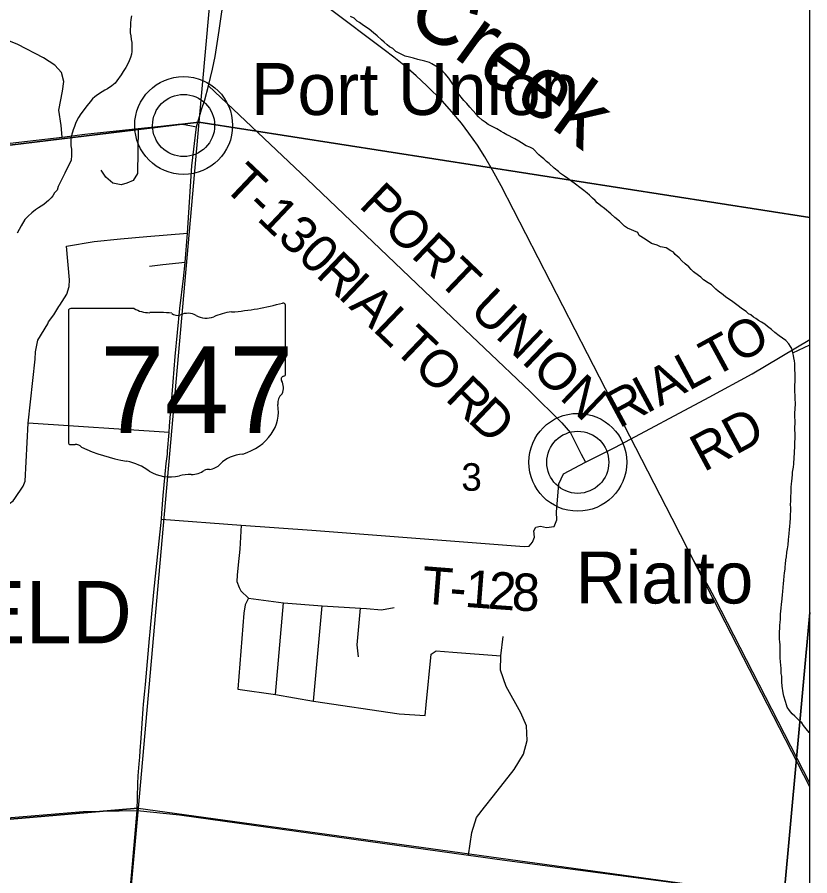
# Model space of a CAD drawing. Extents: x 0 to 34, y 0 to 22.
# Drawn here: x 14.895 to 16.1, y 15.978 to 17.283 of the extents above; entities that cross this region are included whole.
import ezdxf

# ---------------------------------------------------------------- set-up
doc = ezdxf.new("R2010")
doc.units = 0
for name, color, linetype in [('GM_X_City_Street', 7, 'Continuous'), ('GM_X_Corporation_Text', 7, 'Continuous'), ('GM_X_County_Road', 7, 'Continuous'), ('GM_X_Minor_River', 7, 'Continuous'), ('GM_X_Minor_River_Text', 7, 'Continuous'), ('GM_X_Rail_Line', 7, 'Continuous'), ('GM_X_Section', 7, 'Continuous'), ('GM_X_Section_Text', 7, 'Continuous'), ('GM_X_State_Location', 7, 'Continuous'), ('GM_X_State_Route', 7, 'Continuous'), ('GM_X_State_Shield', 7, 'Continuous'), ('GM_X_Township_Road', 7, 'Continuous'), ('GM_X_Township_Road_Text', 7, 'Continuous'), ('GM_X_Unincorporated', 7, 'Continuous'), ('GM_X_Unincorporated_Location', 7, 'Continuous'), ('GM_X_Unincorporated_Text', 7, 'Continuous'), ('SC_Scratch1', 7, 'Continuous'), ('SH_Border', 7, 'Continuous'), ('SH_Cut_Line', 7, 'Continuous')]:
    doc.layers.add(name, color=color, linetype=linetype)

msp = doc.modelspace()

# ---------------------------------------------------------------- linework, layer by layer
at = {"layer": 'GM_X_City_Street'}
msp.add_lwpolyline([(15.1505, 16.9097), (15.1165, 16.9063), (15.0963, 16.904)], dxfattribs=at)
at = {"layer": 'GM_X_County_Road'}
for points in [[(14.1436, 17.001), (14.1445, 17.0008), (14.1638, 17.0005), (14.2063, 17.0054), (14.2291, 17.0101), (14.4268, 17.0339), (14.6089, 17.0566), (14.871, 17.0896), (14.9633, 17.1003), (14.9977, 17.1048), (15.079, 17.1136), (15.1132, 17.1173), (15.1445, 17.1206), (15.1676, 17.1161)], [(14.3436, 16.017), (14.373, 16.0196), (14.3965, 16.0227), (14.4598, 16.0277), (14.5486, 16.036), (14.6938, 16.0496), (14.7399, 16.0541), (14.9953, 16.0752), (15.0772, 16.0771)], [(15.0772, 16.0771), (15.1419, 16.0704), (15.581, 16.009), (15.6033, 16.0059), (15.6248, 16.0028), (15.9656, 15.9577), (16.0732, 15.941)]]:
    msp.add_lwpolyline(points, dxfattribs=at)
at = {"layer": 'GM_X_Minor_River'}
msp.add_line((16.0744, 16.7728), (16.1, 16.7846), dxfattribs=at)
for points in [[(15.0688, 17.2849), (15.0679, 17.2792), (15.067, 17.2743), (15.0666, 17.2591), (15.0676, 17.2545), (15.0685, 17.2491), (15.0692, 17.2442), (15.0694, 17.2392), (15.0693, 17.2347), (15.0691, 17.2305), (15.0686, 17.2267), (15.067, 17.2214), (15.0653, 17.2165), (15.0633, 17.2117), (15.0601, 17.2061), (15.0561, 17.2001), (15.0529, 17.1949), (15.0465, 17.1859), (15.0438, 17.1826), (15.0391, 17.1782), (15.0321, 17.1738), (15.0283, 17.1717), (15.024, 17.1691), (15.017, 17.1648), (15.0131, 17.1619), (15.0096, 17.1586), (15.0057, 17.1541), (15.0013, 17.1486), (14.9919, 17.1359), (14.9883, 17.1303), (14.9854, 17.1247), (14.9838, 17.121), (14.9822, 17.1168), (14.9801, 17.1116), (14.9793, 17.1082), (14.978, 17.1048), (14.9771, 17.1006), (14.9766, 17.0965), (14.9765, 17.0923), (14.9767, 17.087), (14.9774, 17.0824), (14.9778, 17.0725), (14.9769, 17.0653), (14.974, 17.0589), (14.9716, 17.0541), (14.9675, 17.0458), (14.9611, 17.0335), (14.9571, 17.0252), (14.9558, 17.0196), (14.9515, 17.0159), (14.9494, 17.0114), (14.9467, 17.0081), (14.9427, 17.004), (14.9393, 17.0014), (14.9354, 16.9981), (14.9276, 16.9931), (14.9226, 16.9898), (14.9175, 16.9854), (14.9116, 16.9802), (14.9066, 16.9751), (14.901, 16.9657), (14.8978, 16.9601), (14.8949, 16.9545)], [(15.7973, 16.984), (15.7877, 16.9918), (15.7825, 16.9961), (15.7769, 17.0008), (15.7735, 17.0039), (15.7695, 17.0078), (15.765, 17.012), (15.7613, 17.0155), (15.7565, 17.0191), (15.7501, 17.0241), (15.7438, 17.0288), (15.7364, 17.0343), (15.7319, 17.0374), (15.727, 17.041), (15.7211, 17.0453), (15.7177, 17.048), (15.7114, 17.0531), (15.7036, 17.0605), (15.6999, 17.0636), (15.6958, 17.0675), (15.6917, 17.0706), (15.688, 17.0737), (15.6795, 17.0827), (15.6742, 17.085), (15.6686, 17.0871), (15.6615, 17.0918), (15.6574, 17.0945), (15.6514, 17.0981), (15.6477, 17.1), (15.6428, 17.1024), (15.6395, 17.104), (15.6342, 17.1072), (15.6305, 17.1088), (15.6242, 17.1131), (15.6182, 17.1163), (15.6111, 17.1198), (15.6066, 17.123), (15.6017, 17.1261), (15.5962, 17.1315), (15.5925, 17.1354), (15.5877, 17.1408), (15.5832, 17.1459), (15.5784, 17.1517), (15.574, 17.1563), (15.5699, 17.1614), (15.5662, 17.1656), (15.5633, 17.1699), (15.5593, 17.1772), (15.5571, 17.181), (15.5512, 17.1903), (15.5457, 17.1969), (15.542, 17.2), (15.5342, 17.2066), (15.5256, 17.2117), (15.5218, 17.2137), (15.5185, 17.2149), (15.5147, 17.2158), (15.5042, 17.2187), (15.4974, 17.2203), (15.4914, 17.222), (15.485, 17.2236), (15.4797, 17.226), (15.4749, 17.2284), (15.4708, 17.2304), (15.4663, 17.235), (15.4611, 17.2378), (15.4574, 17.2409), (15.4529, 17.2448), (15.4488, 17.2483), (15.4421, 17.2545), (15.4366, 17.2592), (15.4299, 17.2647), (15.4217, 17.2702), (15.4153, 17.2745), (15.412, 17.2769), (15.4072, 17.2815), (15.4015, 17.2839)], [(16.0625, 16.4471), (16.0629, 16.4513), (16.0634, 16.4578), (16.0643, 16.4627), (16.0652, 16.4695), (16.066, 16.4744), (16.0669, 16.4809), (16.0678, 16.4881), (16.0683, 16.4934), (16.0688, 16.4976), (16.0693, 16.5044), (16.0694, 16.5082), (16.0699, 16.5154), (16.0704, 16.5208), (16.0705, 16.5272), (16.071, 16.5314), (16.0711, 16.536), (16.0708, 16.5428), (16.0713, 16.5462), (16.0717, 16.5683), (16.0722, 16.5732), (16.0727, 16.5774), (16.0731, 16.5823), (16.0736, 16.5876), (16.0737, 16.5914), (16.075, 16.599), (16.0755, 16.6036), (16.076, 16.6134), (16.0766, 16.6203), (16.0766, 16.6237), (16.0771, 16.6283), (16.0776, 16.6511), (16.0773, 16.6545), (16.0776, 16.6701), (16.0773, 16.6743), (16.0773, 16.6781), (16.0774, 16.6819), (16.0779, 16.6864), (16.0781, 16.6963), (16.0775, 16.702), (16.0776, 16.7081), (16.0773, 16.7135), (16.0778, 16.7389), (16.0773, 16.7488), (16.0773, 16.7526), (16.077, 16.7564), (16.0767, 16.7602), (16.0757, 16.7648), (16.075, 16.7686), (16.0744, 16.7728), (16.0726, 16.779), (16.0708, 16.7824), (16.0682, 16.7863), (16.0634, 16.7913), (16.0533, 16.7984), (16.047, 16.8035), (16.0418, 16.8078), (16.0358, 16.8128), (16.0314, 16.816), (16.0265, 16.8191), (16.022, 16.8219), (16.0179, 16.8246), (16.0142, 16.827), (16.0101, 16.8301), (16.0067, 16.8321), (16.0034, 16.8352), (15.9974, 16.8391), (15.9892, 16.8454), (15.9829, 16.8501), (15.9792, 16.8524), (15.9725, 16.8571), (15.9684, 16.8606), (15.9606, 16.8665), (15.9572, 16.8692), (15.9505, 16.8758), (15.9453, 16.879), (15.9382, 16.8837), (15.9341, 16.8876), (15.9308, 16.8903), (15.9233, 16.8958), (15.9196, 16.8993), (15.9163, 16.9035), (15.9107, 16.9078), (15.9055, 16.9125), (15.9011, 16.9168), (15.8955, 16.9218), (15.8929, 16.9257), (15.8888, 16.9277), (15.8817, 16.932), (15.8731, 16.9337), (15.8678, 16.9361), (15.8592, 16.9386), (15.8495, 16.9452), (15.8405, 16.9511), (15.8384, 16.9554), (15.8226, 16.9622), (15.8181, 16.9653), (15.8144, 16.9692), (15.8107, 16.9727), (15.8037, 16.9785), (15.7973, 16.984)], [(16.1, 16.1946), (16.099, 16.1957), (16.0945, 16.2011), (16.0905, 16.2062), (16.0879, 16.21), (16.0846, 16.2127), (16.0809, 16.2166), (16.0772, 16.2201), (16.0731, 16.224), (16.069, 16.2287), (16.0657, 16.2341), (16.0643, 16.2375), (16.0629, 16.2425), (16.0604, 16.2509), (16.0594, 16.2559), (16.058, 16.2658), (16.0574, 16.2723), (16.0575, 16.2772), (16.0572, 16.281), (16.0565, 16.2852), (16.0563, 16.2928), (16.0554, 16.3031), (16.0548, 16.3092), (16.055, 16.3214), (16.0548, 16.3294), (16.0545, 16.3328), (16.0538, 16.3378), (16.054, 16.348), (16.0545, 16.3545), (16.0546, 16.3587), (16.0551, 16.3625), (16.0552, 16.3678), (16.0553, 16.3758), (16.0558, 16.3796), (16.0563, 16.3849), (16.0568, 16.3898), (16.0577, 16.3985), (16.0586, 16.4054), (16.059, 16.4092), (16.0596, 16.4164), (16.06, 16.4213), (16.0605, 16.427), (16.061, 16.4331), (16.0615, 16.438), (16.0624, 16.4437), (16.0625, 16.4471)]]:
    msp.add_lwpolyline(points, dxfattribs=at)
at = {"layer": 'GM_X_Rail_Line'}
for points in [[(16.1, 16.1129), (15.9532, 16.3984), (15.8905, 16.5208), (15.7619, 16.7709), (15.6306, 17.0265), (15.6177, 17.0502), (15.6059, 17.0706), (15.5946, 17.0881), (15.5817, 17.1067), (15.5702, 17.1218), (15.5559, 17.1388), (15.5412, 17.1554), (15.5178, 17.1786), (15.5017, 17.1934), (15.4851, 17.2077), (15.4678, 17.2221), (15.453, 17.2332), (15.3691, 17.2959), (15.2224, 17.4044), (14.9335, 17.6179), (14.4589, 17.9682), (14.3622, 18.0403)], [(16.1, 16.1184), (15.9554, 16.3995), (15.9475, 16.415), (15.9218, 16.4597)]]:
    msp.add_lwpolyline(points, dxfattribs=at)
at = {"layer": 'GM_X_Section'}
for points in [[(15.2638, 18.1527), (15.1713, 17.1233), (14.1379, 16.9974), (14.223, 17.9945)], [(14.1379, 16.9974), (15.1713, 17.1233), (15.0788, 16.0806), (14.0511, 15.9925)], [(15.0788, 16.0806), (14.9863, 15.0601), (13.9657, 14.9981), (14.0511, 15.9925)]]:
    msp.add_lwpolyline(points, close=True, dxfattribs=at)
at = {"layer": 'GM_X_State_Route'}
for p, q in [((15.0871, 16.2384), (15.0892, 16.2584)), ((15.0812, 16.1578), (15.082, 16.1678)), ((15.0803, 16.1478), (15.0812, 16.1578))]:
    msp.add_line(p, q, dxfattribs=at)
for points in [[(15.1266, 16.6616), (15.1304, 16.7092), (15.1352, 16.7672), (15.1423, 16.8402), (15.148, 16.8856), (15.1505, 16.9097), (15.1538, 16.9543), (15.1603, 17.0566), (15.1676, 17.1161), (15.1754, 17.1424), (15.1804, 17.1571), (15.1857, 17.1784), (15.1919, 17.2036), (15.1961, 17.2231), (15.202, 17.2627), (15.2102, 17.3192), (15.2168, 17.3724), (15.2212, 17.4049), (15.2277, 17.4487), (15.2286, 17.4566)], [(15.1237, 16.6232), (15.1258, 16.6517), (15.1266, 16.6616)], [(15.1149, 16.5291), (15.1171, 16.5555), (15.1216, 16.6043), (15.1233, 16.6185), (15.1237, 16.6232)], [(15.0971, 16.3485), (15.1026, 16.4088), (15.1097, 16.4768), (15.1142, 16.5197), (15.1149, 16.5291)], [(15.0892, 16.2584), (15.0902, 16.2684), (15.0961, 16.3385), (15.0971, 16.3485)], [(15.082, 16.1678), (15.0837, 16.1868), (15.0864, 16.2314), (15.0871, 16.2384)], [(15.0783, 16.1176), (15.0787, 16.1297), (15.0803, 16.1478)], [(15.0454, 15.7064), (15.0475, 15.7302), (15.0498, 15.7571), (15.0542, 15.8094), (15.0554, 15.8232), (15.0612, 15.8879), (15.0674, 15.9607), (15.0736, 16.0361), (15.0772, 16.0771), (15.0783, 16.1176)]]:
    msp.add_lwpolyline(points, dxfattribs=at)
at = {"layer": 'GM_X_State_Shield'}
for p, q in [((15.0729, 16.84), (14.9763, 16.84)), ((15.3027, 16.7403), (15.3027, 16.845)), ((14.9731, 16.8366), (14.9731, 16.6364)), ((15.3026, 16.7403), (15.3027, 16.7403))]:
    msp.add_line(p, q, dxfattribs=at)
for centre, major_axis, start_param, end_param in [((14.9769, 16.837), (0.00382, 0), 1.712693, 3.28349), ((15.0958, 16.8632), (0.037, 0), 4.042523, 4.731795), ((15.1853, 17.1128), (0.3495, 0), 4.814394, 5.042369), ((15.299, 16.8454), (0.00367, 0), 6.141152, 7.989035), ((15.1081, 16.7277), (0.133, 0), 1.404758, 1.657858), ((15.1383, 16.838), (0.0107, 0), 3.836095, 5.185415), ((15.154, 16.8149), (0.0222, 0), 0.950623, 2.079405), ((15.1827, 16.8466), (0.0267, 0), 4.081561, 5.145723), ((15.2298, 16.7789), (0.0703, 0), 1.699011, 2.107814), ((15.3018, 16.7326), (0.00568, 0), 1.883978, 3.671073), ((15.2988, 16.7399), (0.00393, 0), 5.05454, 6.418171), ((15.2657, 16.7194), (0.0341, 0), 5.934695, 6.695948), ((15.3158, 16.6965), (0.0248, 0), 2.387724, 3.262537), ((15.2048, 16.6831), (0.0874, 0), 5.101752, 6.440018), ((14.9769, 16.636), (0.00385, 0), 3.00124, 4.508301), ((14.9775, 16.6565), (0.0294, 0), 4.665946, 4.897461), ((14.9835, 16.6249), (0.0106, 0), 0.519207, 1.627899), ((15.1173, 16.8047), (0.2524, 0), 4.195997, 4.488961), ((15.2417, 16.5803), (0.0479, 0), 1.647645, 2.488434), ((15.0421, 16.5465), (0.079, 0), 0.823519, 1.323587), ((15.181, 16.617), (0.0282, 0), 4.937069, 5.64225), ((15.1275, 16.6239), (0.0501, 0), 4.026481, 4.996735), ((15.1601, 16.6089), (0.0267, 0), 4.691044, 5.507374), ((15.1843, 16.5895), (0.00752, 0), 1.147584, 2.315152), ((15.1564, 16.5547), (0.0412, 0), 1.495662, 1.94098)]:
    msp.add_ellipse(centre, major_axis=major_axis, ratio=0.8, start_param=start_param, end_param=end_param, dxfattribs=at)
at = {"layer": 'GM_X_Township_Road'}
for p, q in [((15.1258, 16.6517), (14.9119, 16.6657)), ((15.2877, 16.2531), (15.2997, 16.3928)), ((15.3456, 16.2432), (15.3585, 16.3881))]:
    msp.add_line(p, q, dxfattribs=at)
for points in [[(14.9633, 17.1003), (14.9616, 17.1181), (14.9585, 17.1416), (14.9637, 17.1703), (14.9657, 17.1852), (14.9626, 17.1985), (14.9523, 17.21), (14.9348, 17.2209), (14.896, 17.2415), (14.8478, 17.2605), (14.83, 17.2627)], [(15.1857, 17.1784), (15.3356, 17.0365), (15.5361, 16.8455), (15.6746, 16.7136), (15.7231, 16.6663), (15.7362, 16.651), (15.7522, 16.6187), (15.7589, 16.6063)], [(15.079, 17.1136), (15.078, 17.045), (15.0713, 17.0344), (15.0616, 17.0304), (15.0531, 17.0277), (15.0404, 17.0307), (15.0298, 17.0395), (15.0229, 17.0501)], [(14.9597, 16.8451), (14.9705, 16.8618), (14.9741, 16.8733), (14.9747, 16.8833), (14.9702, 16.9345), (15.012, 16.942), (15.0519, 16.946), (15.0922, 16.9493), (15.1538, 16.9543)], [(14.5434, 16.5013), (14.6568, 16.5201), (14.8319, 16.5357), (14.868, 16.5399), (14.8834, 16.5433), (14.8887, 16.5475), (14.8916, 16.5513), (14.9043, 16.5697), (14.9072, 16.5774), (14.9119, 16.6657), (14.9224, 16.7631), (14.923, 16.7743), (14.9266, 16.7918), (14.9417, 16.8169), (14.9427, 16.8198), (14.9505, 16.8303), (14.9584, 16.843), (14.9597, 16.8451)], [(15.7589, 16.6063), (15.8048, 16.6292), (15.9472, 16.7052), (16.0123, 16.7407), (16.1, 16.7929)], [(15.1142, 16.5197), (15.2354, 16.5104), (15.3429, 16.5031), (15.6393, 16.4803), (15.6658, 16.478), (15.6731, 16.4785), (15.6786, 16.4848), (15.6814, 16.4926), (15.6804, 16.5018), (15.6832, 16.5078), (15.6904, 16.5092), (15.6998, 16.507), (15.7114, 16.5084), (15.7156, 16.5186), (15.715, 16.5304), (15.7186, 16.5736), (15.7256, 16.5886), (15.7589, 16.6063)], [(15.2354, 16.5104), (15.2333, 16.4739), (15.2308, 16.4503), (15.2292, 16.4346), (15.2291, 16.425), (15.2325, 16.4159), (15.2352, 16.4109), (15.2466, 16.3999), (15.2997, 16.3928), (15.3585, 16.3881), (15.4168, 16.3844), (15.4259, 16.3837), (15.4488, 16.3821), (15.468, 16.3853)], [(15.2466, 16.3999), (15.2416, 16.3897), (15.2394, 16.3767), (15.2303, 16.2615), (15.2877, 16.2531), (15.3456, 16.2432), (15.4755, 16.2239), (15.515, 16.2215), (15.5166, 16.2375), (15.5241, 16.3144), (15.5317, 16.3195), (15.5572, 16.3176), (15.6302, 16.3118)], [(15.4138, 16.3104), (15.4116, 16.3289), (15.4168, 16.3844)], [(15.619, 16.0991), (15.6506, 16.139), (15.6649, 16.1625), (15.6705, 16.1835), (15.6691, 16.2056), (15.6607, 16.2255), (15.6383, 16.2652), (15.6295, 16.29), (15.6302, 16.3118), (15.6337, 16.3412)], [(15.581, 16.009), (15.5861, 16.0433), (15.5931, 16.0664), (15.6052, 16.0818), (15.619, 16.0991)]]:
    msp.add_lwpolyline(points, dxfattribs=at)
at = {"layer": 'GM_X_Unincorporated'}
for points in [[(16.1, 16.9781), (16.1, 18.0118), (15.2638, 18.1527), (15.1713, 17.1233)], [(16.1, 16.3778), (16.1, 16.9781), (15.1713, 17.1233), (15.0788, 16.0806), (16.0603, 15.9451)], [(16.1, 15.9371), (16.1, 16.3778), (16.0603, 15.9451)]]:
    msp.add_lwpolyline(points, close=True, dxfattribs=at)
for centre, radius in [((15.148, 17.1182), 0.0744), ((15.148, 17.1182), 0.0472), ((15.7472, 16.6062), 0.0744), ((15.7472, 16.6062), 0.0472)]:
    msp.add_circle(centre, radius, dxfattribs=at)
at = {"layer": 'GM_X_Unincorporated_Location'}
for p, q in [((15.148, 17.1182), (15.148, 17.1182)), ((15.7472, 16.6062), (15.7472, 16.6062))]:
    msp.add_line(p, q, dxfattribs=at)
at = {"layer": 'SC_Scratch1'}
msp.add_lwpolyline([(16.1, 14.8738), (16.1, 19.8941), (16.0684, 19.8968), (15.8849, 19.9144), (15.653, 19.9317), (15.4403, 19.9472), (15.2122, 19.9649), (15.0267, 19.9781), (14.9403, 19.9853), (14.9338, 19.9858), (14.6885, 20.0053), (14.609, 20.0113), (14.5282, 20.0174), (14.3921, 20.0277), (14.3035, 19.1497), (14.1911, 17.7706), (14.1894, 17.7492), (14.1791, 17.6233), (14.1287, 17.0041), (14.1092, 16.7637), (14.0483, 15.9927), (14.0411, 15.8502)], dxfattribs=at)
at = {"layer": 'SH_Border'}
msp.add_lwpolyline([(9.3, 20.2361), (9.3, 13.4361), (16.1, 13.4361), (16.1, 20.2361)], close=True, dxfattribs=at)
at = {"layer": 'SH_Cut_Line'}
msp.add_lwpolyline([(16.1, 14.8738), (16.1, 20.2361), (9.3, 20.2361), (9.3, 15.5386)], dxfattribs=at)

# ---------------------------------------------------------------- texts
at = {"layer": 'GM_X_Corporation_Text'}
msp.add_text('FAIRFIELD', height=0.0947, rotation=0, dxfattribs=at).set_placement((14.4221, 16.3311))
at = {"layer": 'GM_X_Minor_River_Text'}
msp.add_text('Creek', height=0.0947, rotation=324.0162, dxfattribs=at).set_placement((15.482, 17.2774))
at = {"layer": 'GM_X_Section_Text'}
msp.add_text('3', height=0.0419, rotation=0, dxfattribs=at).set_placement((15.5702, 16.5629))
at = {"layer": 'GM_X_State_Location'}
for s in ['s', 'r']:
    msp.add_text(s, height=0.000189, dxfattribs=at).set_placement((15.1342, 16.7232))
msp.add_text('747', height=0.000189, rotation=0, dxfattribs=at).set_placement((15.0673, 16.7094))
at = {"layer": 'GM_X_State_Shield'}
msp.add_text('747', height=0.13184, dxfattribs=at).set_placement((15.0209, 16.6506))
at = {"layer": 'GM_X_Township_Road_Text'}
for s, height, rotation, p in [('T-130', 0.05682, 316.5908, (15.2058, 17.0246)), ('PORT UNION', 0.05682, 316.2871, (15.4128, 16.9953)), ('R', 0.0568, 316.2227, (15.3473, 16.8904)), ('I', 0.0568, 316.2199, (15.381, 16.8581)), ('A', 0.0568, 316.2244, (15.3979, 16.8419)), ('L', 0.0568, 316.2213, (15.434, 16.8073)), ('O', 0.0568, 29.8613, (15.9918, 16.7554)), ('T', 0.0568, 316.2245, (15.4647, 16.7779)), ('T', 0.0568, 28.5807, (15.9533, 16.7344)), ('O', 0.0568, 316.2236, (15.4954, 16.7485)), ('L', 0.0568, 28.3353, (15.9157, 16.7141)), ('A', 0.0568, 28.3296, (15.8717, 16.6904)), ('R', 0.0568, 316.266, (15.5441, 16.7018)), ('I', 0.0568, 28.3319, (15.8511, 16.6793)), ('R', 0.0568, 28.33, (15.81, 16.6571)), ('D', 0.0568, 316.5791, (15.5781, 16.6693)), ('RD', 0.05682, 28.3345, (15.9387, 16.5907)), ('T', 0.0568, 355.5492, (15.5085, 16.3917)), ('1', 0.0568, 355.6388, (15.5742, 16.3866)), ('2', 0.0568, 355.915, (15.6094, 16.3839)), ('8', 0.0568, 357.3997, (15.646, 16.3813)), ('-', 0.0568, 355.5666, (15.5509, 16.3884))]:
    msp.add_text(s, height=height, rotation=rotation, dxfattribs=at).set_placement(p)
at = {"layer": 'GM_X_Unincorporated_Text'}
for s, p in [('Port Union', (15.2506, 17.1341)), ('Rialto', (15.744, 16.3916))]:
    msp.add_text(s, height=0.07898, rotation=0, dxfattribs=at).set_placement(p)

doc.saveas('drawing.dxf')
